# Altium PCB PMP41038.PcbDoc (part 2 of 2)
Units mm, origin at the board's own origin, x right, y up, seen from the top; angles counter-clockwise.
Board outline 101.5 x 48.5 mm, 4 copper layers (Top Layer, Signal Layer 1, Signal Layer 2, Bottom Layer), stack 0.713 mm thick; 126 components, 51 nets, 261 pads, 192 vias.
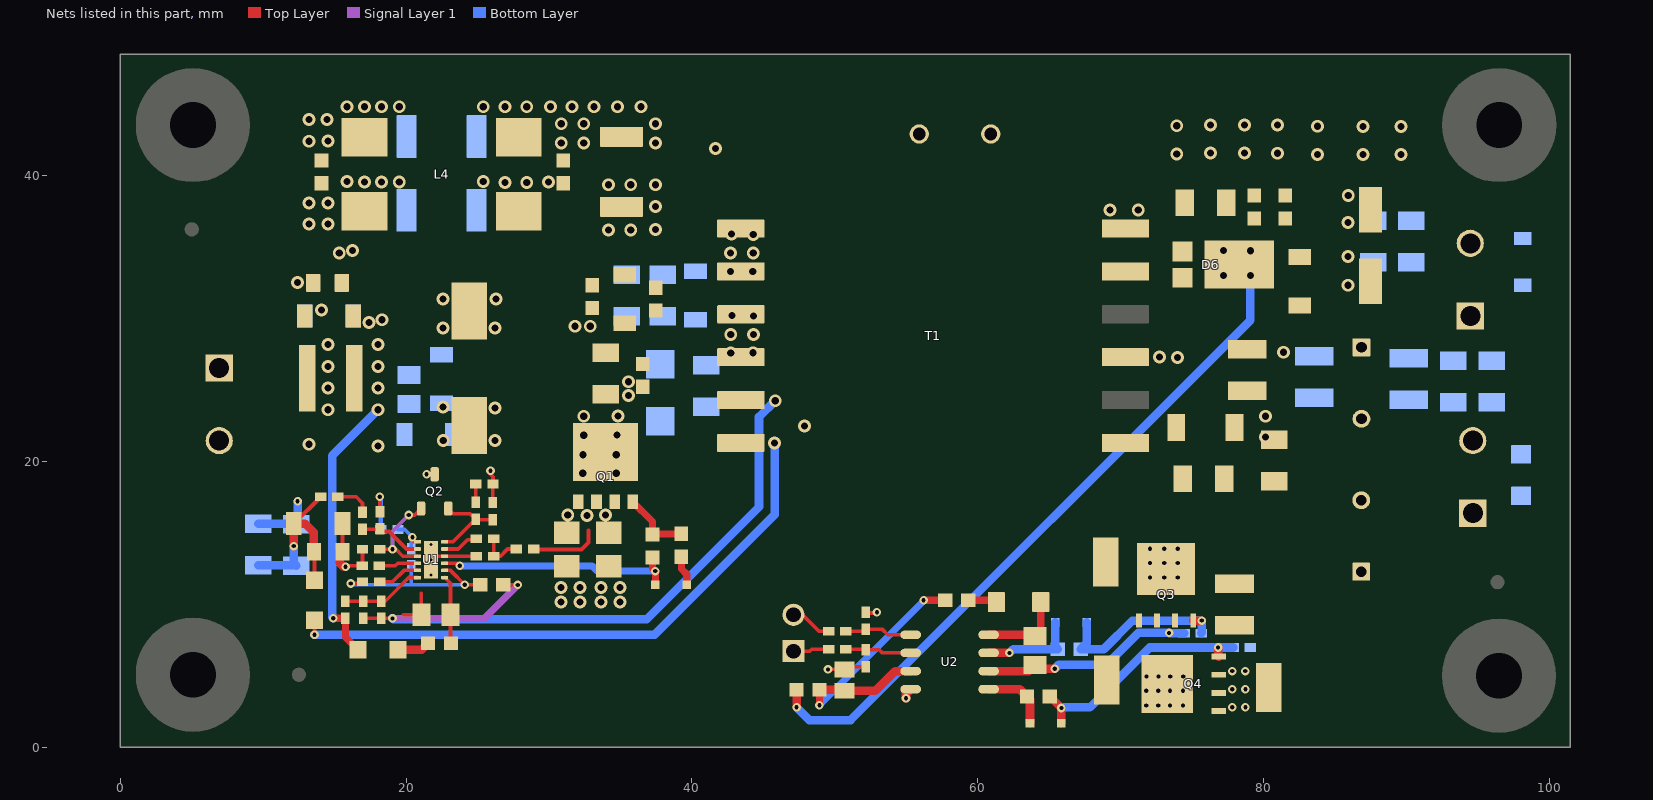
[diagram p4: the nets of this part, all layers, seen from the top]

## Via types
v1: diameter 0.9, hole 0.5, Top Layer to Bottom Layer, 133 vias
v2: diameter 0.6, hole 0.3, Top Layer to Bottom Layer, 56 vias
v3: diameter 0.5, hole 0.2, Top Layer to Bottom Layer, 3 vias

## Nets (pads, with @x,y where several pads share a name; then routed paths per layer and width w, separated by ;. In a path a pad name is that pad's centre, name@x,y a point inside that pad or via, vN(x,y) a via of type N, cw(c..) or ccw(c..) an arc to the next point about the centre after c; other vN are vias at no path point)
12Vo: C19.1 C20.2 C21.1 C23.1 D6.3 D7.1 J3.2 R23.2 R35.2 R36.2 | length 48.1
  Top Layer w0.6: v2(47.333,2.794) R23.2@47.333,4.017 R23.2@47.371,4.055
  Bottom Layer w0.6: v2(47.333,2.794) 48.222,1.905 51.116,1.905 79.096,29.885 v1(79.096,33.013)
  other v1: 77.216,33.02 79.096,34.753 77.216,34.76 85.939,36.728 85.946,38.608
120Vo: C12.2 C13.2 C14.2 C15.2 C16.2 C18.1 C33.1 D1.1 D2.1 J2.2 Q3.5 R37.2 R38.2 TP1.1
  other v1: 80.161,21.708 80.161,23.173
  other v2: 72.065,11.879 73.061,11.879 74.004,11.879 72.066,12.895 73.061,12.895 74.004,12.895 72.066,13.904 73.062,13.904 74.004,13.904
AGND: C22.2 C25.2 C28.2 C29.2 C30.2 C31.2 C38.2 Q2.3 R12.1 R20.2 R21.1 R31.1 R33.1 R34.1 T1.5 | length 65.1
  Top Layer w0.254: C29.2@15.35,13.684 C29.2@15.525,13.859 ; C38.2@15.548,15.658 15.55,15.656 C29.2@15.55,13.684 ; v2@15.88,12.698 16.95,12.698 C28.2@16.95,13.859 ; R12.1@17,9.029 C25.2@18.25,9.029 19.037,9.029 v2(19.049,9.017) ; v2@25.837,19.177 26.086,18.929 C31.2@26.086,18.429 26.075,18.419 C30.2@26.075,17.132 ; C22.2@26.8,11.379 27.794,11.379 v2(27.813,11.361)
  Top Layer w0.3: v2(18.15,17.526) 18.173,17.503 R21.1@18.173,16.49
  Top Layer w0.6: C29.2@15.35,13.684 15.35,12.912 v2@15.633,12.629
  Signal Layer 1 w0.5: v2(19.049,9.017) 25.469,9.017 v2(27.813,11.361)
  Bottom Layer w0.3: v2(18.15,17.526) 18.236,17.44 R20.2@18.236,15.24
  Bottom Layer w0.6: R34.1@9.652,15.637 12.345,15.637 12.407,15.699 v2(12.407,17.224) ; v2(19.049,9.017) 19.095,8.971 30.435,8.971 30.454,8.953 36.83,8.953 44.704,16.827 44.704,23.117 v1(45.844,24.257)
  other v2: 15.763,12.629 21.434,19.107 25.908,19.354
BIAS: C24.1 R6.1 U1.1 | length 4.8
  Top Layer w0.254: U1.1@22.7,11.879 23.106,11.473 C24.1@23.106,9.279 23.106,7.313 R6.1@23.14,7.279
CS: R14.2 U1.5 | length 2.5
  Top Layer w0.254: U1.5@22.7,13.879 23.656,13.879 24.306,14.529 R14.2@24.925,14.529
DPWMH: J4.1 R28.1 | length 2.5
  Top Layer w0.254: J4.1@47.117,6.731 48.26,6.731 48.387,6.858 R28.1@49.573,6.858
DPWML: J4.2 R27.1 | length 2.9
  Top Layer w0.254: J4.2@47.117,9.271 47.752,9.271 48.895,8.128 R27.1@49.573,8.128
FB: R19.1 R21.2 U1.8 | length 4.4
  Top Layer w0.254: R19.1@16.95,15.257 18.14,15.257 R21.2@18.173,15.29 ; R21.2@18.173,15.104 18.805,15.104 20.03,13.879 U1.8@20.8,13.879
GATE: D9.1 R9.1 U1.3 | length 17
  Top Layer w0.254: U1.3@22.7,12.879 23.568,12.879 v2(23.749,12.698)
  Top Layer w0.5: R9.1@37.25,13.289 37.25,12.534 v2(37.449,12.335) D9.1@37.449,11.361
  Bottom Layer w0.5: v2(23.749,12.698) 33.018,12.698 33.382,12.335 v2(37.449,12.335)
GND: C2.2 J1.2 L4.1 L5.1
  other v1: 13.208,36.627 14.525,36.627 13.208,38.1 14.525,38.1 17.09,39.562 18.288,39.562 19.519,39.562 15.875,39.611
HB: C34.1 D10.1 U2.8 | length 5.8
  Top Layer w0.5: C34.1@64.016,7.789 64.423,8.196 D10.1@64.423,10.16
  Top Layer w0.6: U2.8@60.772,7.874 63.931,7.874 C34.1@64.016,7.789
HI: C37.1 R28.2 U2.2 | length 4.7
  Top Layer w0.254: R28.2@50.773,6.858 52.149,6.858 C37.1@52.184,6.823 53.121,6.823 53.34,6.604 U2.2@55.322,6.604
HO: D11.1 R26.1 U2.7 | length 6.9
  Top Layer w0.6: U2.7@60.772,6.604 v2(62.23,6.604)
  Bottom Layer w0.6: v2(62.23,6.604) 62.484,6.858 R26.1@65.621,6.858 65.448,7.031 D11.1@65.448,8.763
HS: C34.2 Q3.1 Q3.2 Q3.3 Q4.5 R25.1 TP2.1 U2.6 | length 15
  Top Layer w0.6: U2.6@60.772,5.334 63.593,5.334 C34.2@64.016,5.757 64.279,5.494 v2(65.405,5.494)
  Bottom Layer w0.6: v2(65.405,5.494) 65.68,5.77 69.016,5.77 71.247,8.001 v2(73.406,8.001) 73.419,7.988 R25.1@74.457,7.988
  other v2: 71.804,2.921 72.64,2.921 73.465,2.921 74.374,2.921 71.804,3.952 72.64,3.952 73.465,3.952 74.374,3.952 71.824,4.953 72.66,4.953 73.485,4.953 74.403,4.953
IS: C26.2 Q1.1 Q1.2 Q1.3 R15.2 R17.2 R18.2 | length 4.9
  Top Layer w0.254: R15.2@28.924,13.879 28.96,13.843 32.278,13.843 32.766,14.331 32.766,15.202
  other v1: 32.66,16.211 31.316,16.256 33.962,16.256 35.573,24.631 35.573,25.583
LI: C36.1 R27.2 U2.1 | length 4.8
  Top Layer w0.254: R27.2@50.773,8.128 52.064,8.128 C36.1@52.184,8.248 53.347,8.248 53.721,7.874 U2.1@55.322,7.874
LO: D12.1 R29.1 U2.5 | length 4.9
  Top Layer w0.254: R29.1@63.335,3.683 R29.1@63.462,3.556
  Top Layer w0.6: U2.5@60.772,4.064 62.954,4.064 R29.1@63.335,3.683 ; R29.1@63.462,3.556 63.67,3.348 D12.1@63.67,1.691
NetC3_1: C3.1 L2.2 L3.1 L4.3
  other v1: 30.861,42.291 32.432,42.291 37.447,42.291 30.861,43.647 32.432,43.647 37.447,43.647 25.4,44.831 26.924,44.831 28.448,44.831 30.099,44.831 31.623,44.831 33.147,44.831 34.798,44.831 36.449,44.831
NetC4_1: C4.1 C5.1 C6.1 L1.1 L3.2
  other v1: 14.525,23.622 14.525,25.146 14.525,26.64 14.525,28.179 14.082,30.607 12.407,32.524 34.158,36.195 35.729,36.195 37.447,36.25 37.447,37.846 34.158,39.37 35.729,39.37 37.447,39.37
NetC10_1: C10.1 R1.1
NetC17_2: C17.2 D4.1 R2.1 R3.1
NetC18_2: C18.2 R5.2
NetC23_2: C23.2 R7.2
NetC26_1: C26.1 R10.1
NetC27_1: C27.1 R14.1 R15.1 | length 3
  Top Layer w0.254: R14.1@26.125,14.529 26.125,13.804 C27.1@26.125,13.379 26.606,13.379 27.106,13.879 R15.1@27.724,13.879
NetC30_1: C30.1 Q2.2 R22.2 U1.6 | length 6.3
  Top Layer w0.254: U1.6@22.7,14.379 23.291,14.379 R22.2@24.866,15.954 ; Q2.2@22.95,16.707 23.31,16.347 24.473,16.347 R22.2@24.866,15.954 ; C30.1@26.075,15.932 24.888,15.932 R22.2@24.866,15.954
NetC31_1: C31.1 R22.1 | length 1.3
  Top Layer w0.254: R22.1@24.866,17.154 24.866,18.409 C31.1@24.886,18.429
NetD2_2: D2.2 R5.1 T1.7
NetD3_1: D3.1 R6.2 | length 2.3
  Top Layer w0.6: D3.1@19.434,6.823 21.084,6.823 R6.2@21.54,7.279
NetD4_2: D4.2 R4.1
NetD6_1: D6.1 D6.2 R7.1 T1.11
NetD8_2: D8.2 T1.6 | length 41.7
  Top Layer w0.254: v2(13.589,7.874) D8.2@13.589,8.887
  Bottom Layer w0.6: v2(13.589,7.874) 37.395,7.874 45.794,16.273 v1(45.794,21.305)
NetD9_2: D9.2 R11.2 | length 2.1
  Top Layer w0.5: R11.2@39.274,13.339 39.274,12.485 39.649,12.11 D9.2@39.649,11.361
NetD10_2: D10.2 R24.2 | length 2
  Top Layer w0.5: R24.2@59.347,10.287 61.196,10.287 D10.2@61.323,10.16
NetD11_2: D11.2 Q3.4 R25.2 R26.2 | length 12.9
  Top Layer w0.6: Q3.4@75.102,8.88 75.116,8.866 v2(75.692,8.866)
  Bottom Layer w0.6: D11.2@67.648,8.763 67.648,7.285 R26.2@67.221,6.858 68.834,6.858 70.842,8.866 v2(75.692,8.866) 75.692,8.023 R25.2@75.657,7.988
NetD12_2: D12.2 Q4.4 R29.2 R30.2 | length 16.7
  Top Layer w0.6: R29.2@65.062,3.556 v2(65.87,2.748) ; D12.2@65.87,1.691 v2(65.87,2.748) ; v2@65.896,2.774 v2(65.87,2.748) ; v2(76.835,6.985) 76.835,6.403 Q4.4@76.888,6.35
  Bottom Layer w0.6: v2(65.87,2.748) 65.915,2.793 67.866,2.793 72.058,6.985 v2(76.835,6.985) R30.2@77.886,6.985
NetQ1_4: Q1.4 R9.2 R11.1 | length 4.9
  Top Layer w0.5: Q1.4@35.867,17.178 37.25,15.794 R9.2@37.25,14.889 37.3,14.939 R11.1@39.274,14.939
NetQ1_5: Q1.5 R4.2 R10.2 T1.3 T1.4
  other v1: 32.365,19.177 34.713,19.181 32.385,20.473 34.713,20.477 32.432,21.844 34.766,21.848 32.432,23.173 34.84,23.176 42.725,27.605 44.295,27.612 42.725,28.902 44.327,28.902 44.327,30.198 42.803,30.226
NetR16_1: R16.1 R19.2 | length 2.5
  Top Layer w0.254: R16.1@15.228,17.526 16.506,17.526 16.95,17.082 R19.2@16.95,16.457
NetR20_1: R20.1 R32.1 U1.7 | length 2.7
  Top Layer w0.254: v2(20.447,14.699) 20.447,14.469 20.536,14.379 U1.7@20.8,14.379
  Bottom Layer w0.254: R20.1@19.436,15.24 19.906,15.24 v2(20.447,14.699) 20.372,14.624 R32.1@20.372,13.894
PGND: C1.2 C3.2 C4.2 C5.2 C6.2 C7.2 C8.2 C9.2 C10.2 C11.2 C24.2 C27.2 C32.2 L4.4 L5.2 R17.1 R18.1 U1.4 U1.13 | length 5.7
  Top Layer w0.254: 19.82,9.279 C24.2@21.074,9.279 21.074,10.787 ; U1.13@22,13.379 U1.4@22.7,13.379 C27.2@24.925,13.379
  other v1: 30.84,10.16 32.169,10.16 33.639,10.16 34.983,10.16 30.84,11.176 32.169,11.176 33.639,11.176 34.983,11.176 18.034,21.086 13.209,21.209 22.606,21.463 26.223,21.463 47.885,22.479 26.223,23.749 22.589,23.806 31.818,29.464 32.891,29.464 17.399,29.739 18.323,29.923 15.32,34.6 16.256,34.76 26.924,39.541 28.448,39.541 29.972,39.562 25.4,39.611 41.656,41.92
  other v3: 21.75,12.054 21.75,13.129 21.75,14.204
PGOOD: R13.1 U1.11 | length 3
  Top Layer w0.254: R13.1@18.15,11.579 19.049,11.579 19.849,12.379 U1.11@20.8,12.379
RT: R33.2 U1.10 | length 2.7
  Top Layer w0.254: R33.2@18.15,12.698 19.25,12.698 19.431,12.879 U1.10@20.8,12.879
SGND: C12.1 C13.1 C14.1 C15.1 C16.1 C19.2 C20.1 C21.2 C32.1 C33.2 C35.2 C36.2 C37.2 D1.2 D7.2 J2.1 J3.1 Q4.1 Q4.2 Q4.3 R30.1 R35.1 R36.1 R37.1 R38.1 T1.9 T1.12 TP3.1 U2.4 | length 4.5
  Top Layer w0.254: v2(49.53,5.449) C35.2@50.673,5.449 50.847,5.623 C37.2@52.184,5.623 ; C35.2@50.566,5.227 C35.2@50.73,5.391 ; C36.2@52.184,9.448 52.434,9.448 52.484,9.398 52.909,9.398 v2(52.959,9.448)
  Top Layer w0.6: v2(54.991,3.429) 54.991,3.733 U2.4@55.322,4.064
  other v1: 74.004,27.292 72.743,27.305 81.407,27.653 85.935,32.337 85.928,34.353 69.279,37.614 71.247,37.614 86.974,41.484 89.641,41.484 83.799,41.497 73.938,41.533 81.005,41.576 76.306,41.594 78.681,41.594 83.799,43.465 86.974,43.451 89.641,43.451 73.938,43.5 81.005,43.543 76.306,43.561 78.681,43.561
  other v2: 77.822,2.793 78.749,2.791 77.822,4.063 78.749,4.061 77.822,5.333 78.74,5.333
SS: C28.1 Q2.1 U1.9 | length 6.8
  Top Layer w0.254: C28.1@18.15,13.859 v2(19.05,13.859) 19.288,13.859 19.768,13.379 U1.9@20.8,13.379 ; v2(20.193,16.256) 20.599,16.256 Q2.1@21.05,16.707
  Signal Layer 1 w0.254: v2(19.05,13.859) 19.05,15.113 v2(20.193,16.256)
UVLO: C25.1 R8.1 R12.2 U1.12 | length 5.7
  Top Layer w0.254: R8.1@15.75,10.229 R12.2@17,10.229 C25.1@18.25,10.229 18.543,10.229 20.193,11.879 U1.12@20.8,11.879
VCC: C22.1 R13.2 R32.2 U1.2 | length 13.1
  Top Layer w0.254: v2(16.129,11.463) 16.834,11.463 R13.2@16.95,11.579 ; U1.2@22.7,12.379 23.107,12.379 v2(24.107,11.379) C22.1@25.2,11.379
  Bottom Layer w0.254: v2(16.129,11.463) 16.213,11.379 20.32,11.379 ; R32.2@20.372,12.694 20.372,11.431 20.32,11.379 ; v2(24.107,11.379) 20.32,11.379
VDD: C35.1 R23.1 R24.1 U2.3 | length 19.9
  Top Layer w0.5: v2(48.933,2.95) R23.1@48.933,4.017 ; v2(56.221,10.287) R24.1@57.747,10.287
  Top Layer w0.6: R23.1@48.933,4.017 50.605,4.017 C35.1@50.673,3.949 52.851,3.949 54.236,5.334 U2.3@55.322,5.334
  Bottom Layer w0.5: v2(48.933,2.95) 56.221,10.238 v2(56.221,10.287)
VIN: C2.1 J1.1 L2.1 L4.2
  other v1: 13.209,42.418 14.525,42.447 13.209,43.942 14.478,43.942 15.875,44.831 17.09,44.831 18.288,44.831 19.519,44.831
VIN_FILTER: C1.1 C7.1 C8.1 C9.1 C11.1 C17.1 D3.2 L1.2 R1.2 R2.2 R3.2 R8.2 T1.1 T1.2 | length 19.4
  Top Layer w0.5: v2(14.91,9.029) R8.2@15.75,9.029 15.75,7.707 D3.2@16.634,6.823
  Bottom Layer w0.6: v2(14.91,9.029) 14.829,9.11 14.829,20.417 v1(18.034,23.622)
  other v1: 18.034,25.146 18.034,26.64 18.034,28.179 22.589,29.337 26.223,29.337 22.589,31.369 26.289,31.369 42.698,33.303 44.267,33.31 42.698,34.6 44.299,34.6 44.299,35.896 42.775,35.924
Vpri: C29.1 C38.1 D8.1 R16.2 R31.2 R34.2 | length 13.3
  Top Layer w0.254: C29.1@13.428,13.684 13.589,13.523 D8.1@13.589,11.853
  Top Layer w0.3: C38.1@12.148,15.658 12.161,15.658 R16.2@14.028,17.526
  Top Layer w0.6: v2(12.148,14.085) C38.1@12.148,15.658 ; C38.1@12.161,15.658 12.928,15.658 13.55,15.036 C29.1@13.55,13.684 C29.1@13.428,13.684
  Bottom Layer w0.6: R34.2@9.652,12.737 R31.2@12.293,12.737 ; v2(12.148,14.085) 12.148,12.881 R31.2@12.293,12.737 ; R31.2@12.319,12.711 R31.2@12.293,12.737
pads on no net: FID1.1 FID2.1 FID3.1 H1.1 H2.1 H3.1 H4.1 H5.0 H6.0 H7.0 H8.0 LBL1.0 T1.8 T1.10

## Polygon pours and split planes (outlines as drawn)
SGND on Top Layer "TOP_LAYER_SGND_P322" (solid, remove dead copper, pour order 322): 75.946,1.524 76.561,0.909 100.457,0.909 100.457,14.351 100.457,32.004 99.06,33.401 92.553,33.401 90.976,34.978 85.257,34.978 81.407,31.127 79.236,28.956 68.58,28.956 68.199,28.575 68.199,26.543 68.58,26.162 80.023,26.162 95.885,26.162 97.282,24.765 97.282,20.066 95.792,18.576 93.252,18.576 90.043,15.367 82.169,15.367 81.534,14.732 81.534,11.239 79.574,9.279 76.533,9.279 75.946,8.692
NetD2_2 on Top Layer "TOP_LAYER_NETD2_2_P298" (solid, remove dead copper, pour order 298): 68.834,19.812 70.883,19.812 71.985,18.71 71.985,17.677 72.39,17.272 74.844,17.272 75.231,17.658 75.231,23.321 74.807,23.745 72.997,23.745 71.985,22.733 68.834,22.733 68.08,21.979 68.08,20.566
NetC23_2 on Top Layer "TOP_LAYER_NETC23_2_P296" (solid, remove dead copper, pour order 296): 78.052,37.328 78.443,37.719 79.566,37.719 80.066,38.219 80.066,39.024 79.617,39.472 76.346,39.472 76.073,39.2 76.073,36.962 76.308,36.728 77.876,36.728 78.052,36.904
NetD8_2 on Top Layer "TOP_LAYER_NETD8_2_P294" (solid, remove dead copper, pour order 294): 41.783,20.066 41.715,20.134 41.715,21.933 42.006,22.225 46.119,22.225 46.482,21.862 46.482,20.477 46.071,20.066
AGND on Top Layer "TOP_LAYER_AGND_P292" (solid, remove dead copper, pour order 292): 41.783,22.987 41.715,23.055 41.715,24.936 41.881,25.103 46.046,25.103 46.348,24.801 46.348,23.393 45.942,22.987
VIN_FILTER on Top Layer "TOP_LAYER_VIN_FILTER_P110" (solid, remove dead copper, pour order 110): 40.35,31.66 45.653,31.66 46.355,32.337 46.355,34.295 46.355,36.87 45.611,37.614 41.812,37.614 38.704,34.506 30.887,34.506 28.832,34.506 27.236,32.91 21.71,32.91 19.177,30.377 19.177,29.522 18.496,28.841 18.48,28.841 15.688,28.841 15.494,28.644 15.494,23.339 15.743,23.091 17.766,23.091 18.88,23.091 22.713,26.924 26.416,26.924 31.152,31.66
VIN on Top Layer "TOP_LAYER_VIN_P084" (solid, remove dead copper, pour order 84): 20.574,40.513 21.021,40.96 21.021,47.178 20.574,47.625 2.794,47.625 0.889,45.72 0.889,25.453 1.958,24.384 6.985,24.384 7.874,25.273 7.874,34.72 13.667,40.513
GND on Top Layer "TOP_LAYER_GND_P082" (solid, remove dead copper, pour order 82): 20.605,40.18 21.021,39.764 21.021,39.718 21.021,36.195 20.576,35.75 14.082,35.75 11.43,33.098 11.43,19.624 10.475,18.669 1.27,18.669 0.889,19.05 0.889,23.123 1.515,23.749 7.112,23.749 8.255,24.892 8.255,34.587 13.848,40.18
SGND on Top Layer "TOP_LAYER_SGND_P064" (solid, remove dead copper, pour order 64): 83.765,39.985 82.007,38.227 81.28,38.227 79.522,39.985 73.231,39.985 72.271,39.025 72.271,35.818 71.696,35.242 68.77,35.242 68.326,35.687 68.326,43.682 69.342,44.698 81.12,44.698 81.136,44.682 90.994,44.682 91.694,43.982 91.694,41.021 90.658,39.985
no net on Top Layer "TOP_LAYER_NONET_P062" (solid, remove dead copper, pour order 62): 67.818,43.776
12Vo on Top Layer "TOP_LAYER_12VO_P060" (solid, remove dead copper, pour order 60): 77.724,35.941 78.486,36.703 78.486,37.396 78.682,37.592 80.627,37.592 82.042,37.592 83.991,39.541 93.009,39.541 93.737,38.813 96.393,38.813 97.028,38.178 97.028,34.544 96.52,34.036 92.931,34.036 91.646,35.32 84.964,35.32 81.325,31.682 76.268,31.682 75.819,32.131 75.819,35.468 76.292,35.941
NetC18_2 on Top Layer "TOP_LAYER_NETC18_2_P056" (solid, remove dead copper, pour order 56): 76.739,17.292 76.415,17.615 76.415,19.541 76.599,19.722 81.142,19.722 81.661,19.202 81.661,17.526 81.427,17.292
120Vo on Top Layer "TOP_LAYER_120VO_P050" (solid, remove dead copper, pour order 50): 68.088,10.414 79.148,10.414 79.629,10.895 79.629,14.692 78.934,15.367 68.206,15.367 67.691,14.866 67.691,10.811
NetD6_1 on Top Layer "TOP_LAYER_NETD6_1_P046" (solid, remove dead copper, pour order 46): 75.329,39.231 74.936,39.624 73.86,39.624 72.94,38.704 72.94,35.427 72.191,34.678 68.658,34.678 68.418,34.438 68.418,32.166 68.961,31.623 74.989,31.623 75.329,31.964 75.329,34.417
HS on Top Layer "TOP_LAYER_HS_P042" (solid, remove dead copper, pour order 42): 72.921,9.596 74.208,9.596 74.45,9.354 74.45,8.068 74.644,7.874 75.187,7.874 75.438,7.623 75.438,7.08 75.438,2.032 75.418,1.614 74.713,0.909 68.613,0.909 67.564,1.958 67.564,9.132 68.028,9.596
PGND on Top Layer "TOP_LAYER_PGND_P040" (solid, remove dead copper, pour order 40): 19.675,10.761 19.675,9.107 19.892,8.89 20.065,8.89 20.21,9.035 20.21,10.16 20.346,10.295 22.479,10.295 22.7,10.516 22.7,12.731 21.645,12.731 20.471,11.557
AGND on Top Layer "TOP_LAYER_AGND_P038" (solid, remove dead copper, pour order 38): 19.622,14.836 22.251,14.836 22.251,16.085 21.25,17.086 21.25,17.469 23.613,17.469 23.876,17.732 23.876,18.669 24.186,18.979 26.162,18.979 26.289,19.106 26.289,19.554 26.158,19.685 15.875,19.685 12.468,19.685 10.668,17.885 10.668,7.747 12.966,5.449 18.276,5.449 19.429,6.602 19.431,9.441 19.221,9.652 18.927,9.652 18.771,9.496 18.771,8.481 18.669,8.381 14.449,8.375 14.443,9.689 14.983,9.689 15.2,9.906 15.196,10.883 16.331,12.018 16.331,12.669 16.079,12.921 14.819,12.921 14.438,12.541 12.735,12.541 12.735,16.404 12.735,17.469 18.791,17.469 18.8,15.658
120Vo on Top Layer "TOP_LAYER_120VO_P034" (solid, remove dead copper, pour order 34): 76.513,25.424 76.743,25.654 95.324,25.654 96.5,24.478 96.5,20.3 95.277,19.077 92.737,19.077 89.813,16.153 86.244,16.153 81.569,20.828 76.81,20.828 76.513,21.125
PGND on Top Layer "TOP_LAYER_PGND_P032" (solid, remove dead copper, pour order 32): 30.113,13.125 30.45,13.462 35.434,13.462 35.701,13.195 35.701,8.509 35.235,8.043 30.576,8.043 30.113,8.513
IS on Top Layer "TOP_LAYER_IS_P030" (solid, remove dead copper, pour order 30): 29.972,17.478 30.573,18.079 34.874,18.079 35.179,17.774 35.179,16.256 35.492,15.943 35.492,14.526 35.189,14.224 30.353,14.224 29.972,14.605
IS on Top Layer "TOP_LAYER_IS_P026" (solid, remove dead copper, pour order 26): 37.003,24.196 37.14,24.196 37.257,24.313 37.257,25.889 37.103,26.044 37.082,26.046 35.373,26.046 35.179,25.853 35.179,24.547 35.531,24.196
NetC26_1 on Top Layer "TOP_LAYER_NETC26_1_P024" (solid, remove dead copper, pour order 24): 32.327,26.624 32.327,28.26 32.595,28.529 37.026,28.529 37.28,28.275 37.28,26.722 36.928,26.37 32.581,26.37
PGND on Top Layer "TOP_LAYER_PGND_P022" (solid, remove dead copper, pour order 22): 36.419,31.369 38.1,31.373 38.377,31.095 38.377,29.188 38.018,28.829 36.368,28.829 32.298,28.829 32.057,29.071 32.057,30.926 32.5,31.369
NetQ1_5 on Top Layer "TOP_LAYER_NETQ1_5_P020" (solid, remove dead copper, pour order 20): 41.29,21.408 41.29,25.103 41.715,25.527 45.325,25.527 46,26.162 46,30.835 45.688,31.147 39.529,31.147 38.862,30.48 38.862,28.644 37.941,27.723 37.941,24.053 37.694,23.806 35.135,23.806 34.925,24.016 34.925,25.356 34.501,25.781 31.384,25.781 31.115,25.512 31.115,18.796 31.369,18.542 37.719,18.542 38.481,19.304 40.894,19.304 41.29,19.7
no net on Top Layer "TOP_LAYER_NONET_P018" (solid, remove dead copper, pour order 18): 24.73,22.352
PGND on Top Layer "TOP_LAYER_PGND_P016" (solid, remove dead copper, pour order 16): 30.226,26.691 32.364,28.829 32.766,29.231 32.766,31.369 31.613,31.369 26.759,26.515 23.154,26.515 22.946,26.515 19.182,22.751 19.103,22.672 12.117,22.672 11.754,22.309 11.754,20.416 12.232,19.939 29.718,19.939 30.226,20.447
NetC4_1 on Top Layer "TOP_LAYER_NETC4_1_P012" (solid, remove dead copper, pour order 12): 32.66,36.25 32.66,39.435 33.475,40.25 33.545,40.18 37.67,40.18 38.377,39.473 38.377,36.271 37.412,35.306 33.694,35.306 33.25,35.75
NetC3_1 on Top Layer "TOP_LAYER_NETC3_1_P008" (solid, remove dead copper, pour order 8): 24.542,45.593 37.622,45.593 38.377,44.838 38.377,41.248 37.629,40.5 24.486,40.5 23.876,41.11 23.876,44.927
PGND on Top Layer "TOP_LAYER_PGND_P002" (solid, remove dead copper, pour order 2): 18.863,30.674 18.863,29.774 18.249,29.16 15.273,29.16 14.807,29.626 14.807,34.866 15.191,35.25 20.592,35.25 21.941,36.599 23.582,36.599 23.876,36.89 23.876,39.534 24.522,40.18 31.707,40.18 32.365,39.522 32.365,36.627 30.639,34.901 28.756,34.901 27.129,33.274 21.463,33.274
NetC4_1 on Top Layer "TOP_LAYER_NETC4_1_P000" (solid, remove dead copper, pour order 0): 14.525,29.393 14.525,29.389 15.191,28.723 15.191,23.366 14.916,23.091 14.225,23.091 12.192,23.091 11.811,23.472 11.811,23.495 11.811,33.098 13.003,34.29 14.21,34.29 14.525,33.975
PGND on Signal Layer 1 "SIGNAL_LAYER_1_PGND_P308" (solid, remove dead copper, pour order 308): 1.016,1.27 1.016,47.117 1.524,47.625 57.404,47.625 58.039,46.99 58.039,13.87 57.123,12.954 46.723,12.954 44.327,10.558 44.327,2.544 43.053,1.27
SGND on Signal Layer 1 "SIGNAL_LAYER_1_SGND_P284" (solid, remove dead copper, pour order 284): 46.736,1.143 45.733,2.146 45.733,9.792 47.371,11.43 57.658,11.43 59.563,13.335 59.563,46.482 60.706,47.625 98.298,47.625 100.711,45.212 100.711,4.018 97.836,1.143
VIN_FILTER on Signal Layer 1 "SIGNAL_LAYER_1_VIN_FILTER_P232" (solid, remove dead copper, pour order 232): 17.792,28.841 17.272,28.321 17.272,23.585 17.766,23.091 18.88,23.091 22.713,26.924 26.416,26.924 31.152,31.66 45.413,31.66 46,32.207 46,34.045 46,35.634 44.931,36.703 42.343,36.703 40.146,34.506 30.887,34.506 28.832,34.506 26.33,32.004 20.804,32.004 19.177,30.377 19.177,29.522 18.496,28.841 18.48,28.841
AGND on Signal Layer 1 "SIGNAL_LAYER_1_AGND_P076" (solid, remove dead copper, pour order 76): 18.161,6.985 18.161,7.023 19.519,8.381 19.519,10.756 20.066,11.303 20.767,11.303 21.021,11.557 21.021,14.286 21.848,15.113 26.58,15.113 26.924,15.457 26.924,19.354 26.593,19.685 12.446,19.685 10.668,17.907 10.668,7.747 11.43,6.985
NetC4_1 on Signal Layer 1 "SIGNAL_LAYER_1_NETC4_1_P152" (solid, remove dead copper, pour order 152): 14.525,29.393 14.525,29.389 15.191,28.723 15.191,23.366 14.916,23.091 14.225,23.091 12.192,23.091 11.811,23.472 11.811,23.495 11.811,33.098 13.003,34.29 14.21,34.29 14.525,33.975
PGND on Signal Layer 1 "SIGNAL_LAYER_1_PGND_P150" (solid, remove dead copper, pour order 150): 18.863,30.674 18.863,29.774 18.249,29.16 15.273,29.16 14.807,29.626 14.807,34.866 15.191,35.25 20.592,35.25 21.941,36.599 23.582,36.599 23.876,36.89 23.876,39.534 24.522,40.18 31.707,40.18 32.365,39.522 32.365,36.627 30.639,34.901 28.756,34.901 26.367,32.512 20.701,32.512
NetC4_1 on Signal Layer 1 "SIGNAL_LAYER_1_NETC4_1_P148" (solid, remove dead copper, pour order 148): 32.66,36.25 32.66,39.435 33.475,40.25 33.545,40.18 37.67,40.18 38.377,39.473 38.377,36.271 37.683,35.577 33.423,35.577 33.25,35.75
IS on Signal Layer 1 "SIGNAL_LAYER_1_IS_P124" (solid, remove dead copper, pour order 124): 30.438,15.973 30.917,15.493 36.431,15.493 37,16.063 37,25.931 36.642,26.289 30.948,26.289 30.474,25.815
NetC3_1 on Signal Layer 1 "SIGNAL_LAYER_1_NETC3_1_P118" (solid, remove dead copper, pour order 118): 24.542,45.593 37.622,45.593 38.377,44.838 38.377,41.248 37.629,40.5 24.486,40.5 23.876,41.11 23.876,44.927
GND on Signal Layer 1 "SIGNAL_LAYER_1_GND_P080" (solid, remove dead copper, pour order 80): 20.605,40.18 21.021,39.764 21.021,39.718 21.021,36.195 20.576,35.75 14.082,35.75 11.43,33.098 11.43,19.624 10.475,18.669 1.27,18.669 0.889,19.05 0.889,23.123 1.515,23.749 7.112,23.749 8.255,24.892 8.255,34.587 13.848,40.18
VIN on Signal Layer 1 "SIGNAL_LAYER_1_VIN_P078" (solid, remove dead copper, pour order 78): 20.574,40.513 21.021,40.96 21.021,47.178 20.574,47.625 2.794,47.625 0.889,45.72 0.889,25.453 1.958,24.384 6.985,24.384 7.874,25.273 7.874,34.72 13.667,40.513
SGND on Signal Layer 2 "SIGNAL_LAYER_2_SGND_P312" (solid, remove dead copper, pour order 312): 46.863,1.143 45.733,2.273 45.733,9.792 47.371,11.43 57.658,11.43 59.563,13.335 59.563,46.355 60.706,47.498 100.457,47.498 100.457,1.143
PGND on Signal Layer 2 "SIGNAL_LAYER_2_PGND_P310" (solid, remove dead copper, pour order 310): 1.016,1.27 1.016,47.117 1.524,47.625 56.896,47.625 58.039,46.482 58.039,13.87 57.123,12.954 46.723,12.954 44.327,10.558 44.327,2.544 43.053,1.27
VIN_FILTER on Signal Layer 2 "SIGNAL_LAYER_2_VIN_FILTER_P306" (solid, remove dead copper, pour order 306): 18.88,23.091 18.58,23.091 17.766,23.091 17.676,23.091 17.227,23.54 17.227,28.276 17.792,28.841 18.496,28.841 19.177,29.522 19.177,29.537 21.644,32.004 26.33,32.004 28.832,34.506 30.887,34.506 39.161,34.506 42.246,37.592 45.529,37.592 46,37.121 46,34.045 46,32.345 45.294,31.66 31.158,31.66 26.422,26.924 22.713,26.924
NetC4_1 on Signal Layer 2 "SIGNAL_LAYER_2_NETC4_1_P304" (solid, remove dead copper, pour order 304): 15.958,29.16 17.336,30.538 18.678,30.538 18.684,30.544 19.633,30.544 21.601,32.512 26.367,32.512 28.756,34.901 30.639,34.901 35.306,34.901 35.306,40.18 31.377,40.18 30.988,39.791 30.988,39.224 30.499,38.735 25.721,38.735 23.876,36.89 23.609,36.627 21.969,36.627 20.592,35.25 15.191,35.25 13.667,33.726 13.667,29.16
NetC3_1 on Signal Layer 2 "SIGNAL_LAYER_2_NETC3_1_P202" (solid, remove dead copper, pour order 202): 24.542,45.593 37.622,45.593 38.377,44.838 38.377,41.248 37.629,40.5 24.486,40.5 23.876,41.11 23.876,44.927
NetC4_1 on Signal Layer 2 "SIGNAL_LAYER_2_NETC4_1_P158" (solid, remove dead copper, pour order 158): 13.963,35.25 19.051,35.25 19.194,35.107 19.194,34.316 15.191,34.316 15.191,28.723 15.191,23.366 14.916,23.091 14.225,23.091 12.192,23.091 11.811,23.472 11.811,23.495 11.811,33.098
NetC4_1 on Signal Layer 2 "SIGNAL_LAYER_2_NETC4_1_P154" (solid, remove dead copper, pour order 154): 32.66,36.25 32.66,39.435 33.405,40.18 37.67,40.18 38.377,39.473 38.377,35.458 37.845,34.925 34.075,34.925 33.25,35.75
VIN on Signal Layer 2 "SIGNAL_LAYER_2_VIN_P104" (solid, remove dead copper, pour order 104): 20.574,40.513 21.021,40.96 21.021,47.178 20.574,47.625 2.794,47.625 0.889,45.72 0.889,25.453 1.958,24.384 6.985,24.384 7.874,25.273 7.874,34.72 13.667,40.513
GND on Signal Layer 2 "SIGNAL_LAYER_2_GND_P102" (solid, remove dead copper, pour order 102): 20.605,40.18 21.021,39.764 21.021,39.718 21.021,36.195 20.576,35.75 14.082,35.75 11.43,33.098 11.43,19.624 10.475,18.669 1.27,18.669 0.889,19.05 0.889,23.123 1.515,23.749 7.112,23.749 8.255,24.892 8.255,34.587 13.848,40.18
SGND on Bottom Layer "BOTTOM_LAYER_SGND_P324" (solid, remove dead copper, pour order 324): 46.355,1.016 45.352,2.019 45.352,9.665 46.99,11.303 57.277,11.303 59.182,13.208 59.182,46.355 60.325,47.498 97.917,47.498 100.33,45.085 100.33,3.891 97.455,1.016
12Vo on Bottom Layer "BOTTOM_LAYER_12VO_P320" (solid, remove dead copper, pour order 320): 77.724,35.941 78.486,36.703 78.486,37.396 78.682,37.592 80.627,37.592 82.042,37.592 83.991,39.541 93.009,39.541 93.737,38.813 98.347,38.813 99.06,38.1 99.06,34.544 98.552,34.036 92.931,34.036 91.646,35.32 84.964,35.32 81.325,31.682 76.268,31.682 75.819,32.131 75.819,35.468 76.292,35.941
NetD4_2 on Bottom Layer "BOTTOM_LAYER_NETD4_2_P128" (solid, remove dead copper, pour order 128): 39.322,21.699 39.304,21.717 36.65,21.717 36.3,22.03 36.3,23.981 36.576,24.257 39.524,24.257 39.878,24.611 39.878,24.638 42.183,24.638 42.246,24.575 42.209,24.537 42.209,21.973 41.934,21.699
120Vo on Bottom Layer "BOTTOM_LAYER_120VO_P248" (solid, remove dead copper, pour order 248): 69.596,14.598 69.596,10.922 70.104,10.414 79.375,10.414 85.471,16.51 90.764,16.51 92.329,18.075 93.314,19.077 98.911,19.077 99.568,19.735 99.568,24.511 98.933,25.146 80.144,25.146
NetQ1_5 on Bottom Layer "BOTTOM_LAYER_NETQ1_5_P240" (solid, remove dead copper, pour order 240): 31.249,19.146 31.249,23.873 31.711,24.335 34.339,24.335 34.868,23.806 34.868,18.442 34.333,17.907 31.75,17.907 31.75,17.927 31.242,18.435
PGND on Bottom Layer "BOTTOM_LAYER_PGND_P228" (solid, remove dead copper, pour order 228): 56.515,27.12 56.505,27.11 56.505,18.823 54.264,16.581 46.061,16.666 45.974,16.579 40.005,10.61 40.005,1.524 38.989,0.508 1.079,0.508 0.635,0.953 0.635,17.724 1.326,18.415 10.5,18.415 10.5,18.44 11.684,19.624 11.684,22.86 21.426,22.86 21.554,22.897 21.557,25.125 22.946,26.515 23.154,26.515 26.515,26.515 31.369,31.369 33.611,31.369 38.583,36.342 38.583,45.586 38.481,45.688 39.783,46.99 53.968,46.99 56.515,44.443
NetC10_1 on Bottom Layer "BOTTOM_LAYER_NETC10_1_P226" (solid, remove dead copper, pour order 226): 19.194,20.325 19.194,24.771 19.43,25.007 21.006,25.007 21.209,24.804 21.209,20.338 20.937,20.066 19.453,20.066
VIN_FILTER on Bottom Layer "BOTTOM_LAYER_VIN_FILTER_P206" (solid, remove dead copper, pour order 206): 45.294,31.66 46,32.345 46,34.045 46,37.121 45.529,37.592 42.246,37.592 39.161,34.506 30.887,34.506 28.832,34.506 26.33,32.004 21.644,32.004 19.177,29.537 19.177,29.522 18.496,28.841 18.48,28.841 15.688,28.841 15.494,28.644 15.494,23.368 15.771,23.091 17.766,23.091 18.58,23.091 18.927,23.438 18.927,24.897 19.303,25.273 19.675,25.273 21.068,25.279 22.713,26.924 26.422,26.924 31.158,31.66
NetC3_1 on Bottom Layer "BOTTOM_LAYER_NETC3_1_P204" (solid, remove dead copper, pour order 204): 24.542,45.593 37.622,45.593 38.377,44.838 38.377,41.248 37.629,40.5 24.486,40.5 23.876,41.11 23.876,44.927
NetC4_1 on Bottom Layer "BOTTOM_LAYER_NETC4_1_P164" (solid, remove dead copper, pour order 164): 15.191,29.457 15.191,23.366 14.916,23.091 14.225,23.091 12.192,23.091 11.811,23.472 11.811,23.495 11.811,33.098 13.872,35.159 15.191,35.159
NetC4_1 on Bottom Layer "BOTTOM_LAYER_NETC4_1_P162" (solid, remove dead copper, pour order 162): 30.639,34.901 35.306,34.901 35.306,40.18 24.522,40.18 23.876,39.534 23.876,36.89 23.609,36.627 21.969,36.627 20.592,35.25 15.191,35.25 13.667,33.726 13.667,29.16 18.249,29.16 18.863,29.774 21.601,32.512 26.367,32.512 28.756,34.901
NetC4_1 on Bottom Layer "BOTTOM_LAYER_NETC4_1_P160" (solid, remove dead copper, pour order 160): 32.66,36.25 32.66,39.435 33.405,40.18 37.67,40.18 38.377,39.473 38.377,35.656 37.646,34.925 34.075,34.925 33.25,35.75
NetQ1_5 on Bottom Layer "BOTTOM_LAYER_NETQ1_5_P130" (solid, remove dead copper, pour order 130): 41.485,28.658 40.259,27.432 40.259,26.319 40.543,26.035 45.395,26.035 46,26.64 46,30.642 45.527,31.115 41.783,31.115 41.485,30.817
NetC17_2 on Bottom Layer "BOTTOM_LAYER_NETC17_2_P126" (solid, remove dead copper, pour order 126): 41.03,28.965 39.37,27.305 39.37,25.622 38.755,25.007 36.842,25.007 36.449,25.4 36.449,26.289 34.25,28.488 34.249,31.005 34.613,31.369 40.542,31.369 41.03,30.881
VIN on Bottom Layer "BOTTOM_LAYER_VIN_P108" (solid, remove dead copper, pour order 108): 20.574,40.513 21.021,40.96 21.021,47.178 20.574,47.625 2.794,47.625 0.889,45.72 0.889,25.453 1.958,24.384 6.985,24.384 7.874,25.273 7.874,34.72 13.667,40.513
GND on Bottom Layer "BOTTOM_LAYER_GND_P106" (solid, remove dead copper, pour order 106): 20.605,40.18 21.021,39.764 21.021,39.718 21.021,36.195 20.576,35.75 14.082,35.75 11.43,33.098 11.43,19.624 10.475,18.669 1.27,18.669 0.889,19.05 0.889,23.123 1.515,23.749 7.112,23.749 8.255,24.892 8.255,34.587 13.848,40.18

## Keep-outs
Keep-Out Layer:
  text ".Layer_Name" at 14.656,-21.806 h1.52

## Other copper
Top Layer:
  rectangle net AGND: 21.25,14.224 22.251,15.494
  region: 18.161,7.874
  region: 17.653,7.493
  text ".Layer_Name" at 14.656,-21.806 h1.52
Signal Layer 1:
  pour cut-out: 12.7,13.943
Bottom Layer:
  region net PGND: 15.732,29.16 15.666,29.227 15.666,30.984 15.849,31.168 18.378,31.168 18.796,30.75 18.796,29.616 18.34,29.16 18.249,29.16
  region net PGND: 23.965,36.378 23.965,39.623 24.474,40.132 30.272,40.132 30.682,39.722 30.682,39.302 29.861,38.481 27.069,38.481 25.876,37.288 25.876,36.29 25.586,36 24.343,36
  text ".Layer_Name" at 14.656,-21.806 h1.52

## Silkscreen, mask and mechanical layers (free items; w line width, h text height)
Top Overlay:
  text "PMP41038E1" at 10.389,1.27 h2.75
  text ".Layer_Name" at 14.656,-21.806 h1.52
Bottom Overlay:
  text ".Layer_Name" at 14.656,-21.806 h1.52
Top Paste:
  text ".Layer_Name" at 14.656,-21.806 h1.52
Bottom Paste:
  text ".Layer_Name" at 14.656,-21.806 h1.52
Top Solder:
  text ".Layer_Name" at 14.656,-21.806 h1.52
  text ".Layer_Name" at 14.656,-21.806 h1.52
Bottom Solder:
  text ".Layer_Name" at 14.656,-21.806 h1.52
Drill Guide:
  text ".Layer_Name" at 14.656,-21.806 h1.52
M1 Board Outline:
  the board outline again, w0.254
  text ".Layer_Name" at 14.656,-21.806 h1.52
M2 Board Dimensions:
  rectangle: 0,-6.985 3.175,-3.81
  rectangle: 3.175,-10.16 12.7,-6.985
  lines w0.178: 0,-6.985 25.4,-6.985 ; 3.175,-10.16 3.175,-3.81 ; 6.35,-10.16 6.35,-3.81 ; 12.7,-10.16 12.7,-3.81 ; 19.05,-10.16 19.05,-3.81 ; 0,-10.16 25.4,-10.16 25.4,-3.81 0,-3.81 0,-10.16
  text ".Layer_Name" at 14.656,-21.806 h1.52
M3 3D STEP Top:
  text ".Layer_Name" at 14.656,-21.806 h1.52
M4 3D STEP Bottom:
  text ".Layer_Name" at 14.656,-21.806 h1.52
M5 Assembly Top:
  lines w0.254: -7.417,-23.626 160.223,-23.626 ; -7.417,-18.462 160.274,-18.462 ; -7.417,-13.297 -7.417,-28.791 94.31,-28.791 160.274,-28.791 160.274,-13.297 -7.404,-13.297 -7.404,-28.791 32.614,-28.791 ; 55.194,-28.791 55.194,-13.297 ; 87.376,-18.462 87.376,-13.297 ; 108.712,-18.462 108.712,-13.297 ; 124.511,-28.956 124.511,-23.804
  text "COMPONENTS MARKED 'DNP' SHOULD NOT BE POPULATED." at 29.299,-8.09 h1.52
  text "ASSEMBLY VARIANT:" at 29.286,-11.024 h1.52
  text ".VariantName" at 55.601,-11.024 h1.52
  text "PCB VIEWED FROM TOP SIDE" at -5.804,-16.654 h1.52
  text "BOARD #:" at 57.099,-16.654 h1.52
  text ".PRJ_Number" at 70.955,-16.654 h1.52
  text "REV:" at 92.405,-16.654 h1.52
  text ".PCB_Rev" at 99.809,-16.654 h1.52
  text "SVN REV:" at 113.69,-16.654 h1.52
  text ".VersionControl_RevNumber" at 126.543,-16.654 h1.52
  text "TID #:" at 57.099,-21.819 h1.52
  text ".TID" at 70.955,-21.819 h1.52
  text "PLOT NAME =" at -5.804,-27.034 h1.52
  text ".plot_File_Name" at 14.656,-27.034 h1.52
  text "GENERATED    :" at 57.15,-27.034 h1.52
  text ".Print_Date" at 79.235,-27.034 h1.52
  text ".Print_Time" at 97.752,-27.034 h1.52
  text "TEXAS INSTRUMENTS" at 129.87,-27.034 h1.52
M6 Assembly Bottom:
  lines w0.254: -7.429,-18.474 160.261,-18.474 ; -7.379,-23.639 160.261,-23.639 ; 28.334,-28.969 28.334,-23.817 ; 44.133,-18.474 44.133,-13.31 ; 65.468,-18.474 65.468,-13.31 ; 97.65,-28.804 97.65,-13.31 ; 120.231,-28.804 160.249,-28.804 160.249,-13.31 -7.429,-13.31 -7.429,-28.804 58.534,-28.804 160.261,-28.804 160.261,-13.31
  text "COMPONENTS MARKED 'DNP' SHOULD NOT BE POPULATED." at 154.991,-8.077 h1.52
  text ".VariantName" at 128.473,-11.024 h1.52
  text "ASSEMBLY VARIANT:" at 154.864,-11.024 h1.52
  text ".VersionControl_RevNumber" at 26.302,-16.667 h1.52
  text "SVN REV:" at 39.154,-16.667 h1.52
  text ".PCB_Rev" at 53.035,-16.667 h1.52
  text "REV:" at 60.439,-16.667 h1.52
  text ".PRJ_Number" at 81.89,-16.667 h1.52
  text "BOARD #:" at 95.745,-16.667 h1.52
  text "PCB VIEWED FROM BOTTOM SIDE" at 158.648,-16.667 h1.52
  text ".TID" at 81.89,-21.831 h1.52
  text "TID #:" at 95.745,-21.831 h1.52
  text "TEXAS INSTRUMENTS" at 22.974,-27.047 h1.52
  text ".Print_Time" at 55.093,-27.047 h1.52
  text ".Print_Date" at 73.609,-27.047 h1.52
  text "GENERATED    :" at 95.694,-27.047 h1.52
  text ".plot_File_Name" at 138.189,-27.047 h1.52
  text "PLOT NAME =" at 158.648,-27.047 h1.52
M9 Title Sheet:
  drawing of 57 lines, arcs and shapes, not listed
  text "1" at 18.792,204.127 h1.78
  text "2" at 82.182,204.127 h1.78
  text "3" at 145.411,204.127 h1.78
  text "4" at 209.08,204.127 h1.78
  text "5" at 272.555,204.127 h1.78
  text "6" at 336.182,204.127 h1.78
  text "A" at -10.579,175.095 h1.78
  text "A" at 365.341,175.095 h1.78
  text "B" at -10.579,114.643 h1.78
  text "B" at 365.341,114.643 h1.78
  text "C" at -10.579,54.318 h1.78
  text "C" at 365.341,54.318 h1.78
  text "PROJECT TITLE:" at 288.125,7.048 h1.14
  text ".PRJ_Title" at 289.395,3.662 h1.78
  text "DESIGNED FOR:" at 288.125,-0.597 h1.14
  text ".PRJ_Customer" at 289.395,-4.153 h1.78
  text "D" at -10.579,-5.88 h1.78
  text "D" at 365.341,-5.88 h1.78
  text "FILE NAME:" at 288.125,-8.217 h1.14
  text ".PCB_File_Name_No_Path" at 289.395,-11.265 h1.78
  text "Texas Instruments (TI) and/or its licensors do not warrant the accuracy or completeness of this specification" at 161.9,-15.376 h1.14
  text "ENGINEER:" at 288.125,-15.583 h1.14
  text "LAYOUT BY:" at 326.352,-15.583 h1.14
  text "or any information contained therein. TI and/or its licensors do not warrant that this design will meet" at 160.757,-18.237 h1.14
  text ".PRJ_Engineer" at 289.395,-19.52 h1.78
  text ".PCB_Layout" at 327.635,-19.52 h1.78
  text "the specifications, will be suitable for your application or fit for any particular purpose, or will operate in" at 160.757,-21.099 h1.14
  text ".Layer_Name" at 14.656,-21.806 h1.52
  text "ALTIUM DESIGNER VERSION:" at 326.352,-23.457 h1.14
  text "an implementation. TI and/or its licensors do not warrant that the design is production worthy. You should" at 160.757,-23.961 h1.14
  text "completely validate and test your design implementation to confirm the system functionality for your application." at 161.9,-26.822 h1.14
  text ".print_Scale" at 289.395,-26.843 h1.78
  text ".Application_BuildNumber" at 327.635,-26.843 h1.78
  text "1" at 18.792,-32.093 h1.78
  text "2" at 82.182,-32.093 h1.78
  text "3" at 145.411,-32.093 h1.78
  text "4" at 209.08,-32.093 h1.78
  text "5" at 272.555,-32.093 h1.78
  text "6" at 336.182,-32.093 h1.78
M10 Fab Notes:
  drawing of 189 lines, arcs and shapes, not listed
  text "DESIGN INFORMATION" at 314.503,161.447 h1.52
  text "MIN. TRACK WIDTH:" at 298.131,158.091 h1.52
  text "8" at 325.976,158.091 h1.52
  text "MIL" at 329.907,158.091 h1.52
  text "7.874" at 321.75,155 h1.52
  text "MIN. CLEARANCE:" at 298.131,154.938 h1.52
  text "MIL" at 329.907,154.938 h1.52
  text "MIN. VIA PAD SIZE:" at 298.131,151.785 h1.52
  text "24" at 325.214,151.785 h1.52
  text "MIL" at 329.907,151.785 h1.52
  text "0.05mm (2MIL)" at 315.784,148.486 h1.52
  text "MINIMUM ANNULAR RING" at 289.769,148.277 h1.52
  text "EXTERNAL" at 333.768,148.277 h1.52
  text "PER" at 294.849,145.48 h1.52
  text "IPC-D-275 CLASS 2 LEVEL C" at 300.437,145.48 h1.52
  text "MIL, HOLES" at 338.238,142.928 h1.52
  text "+/-" at 328.27,142.709 h1.52
  text "+/-" at 349.961,142.709 h1.52
  text "REGISTRATION TOLERANCES:" at 289.769,142.682 h1.52
  text "METAL" at 320.243,142.682 h1.52
  text "5" at 334.879,142.683 h1.52
  text "3" at 356.037,142.683 h1.52
  text "MIL" at 358.99,142.682 h1.52
  text "HOLE SIZE TOLERANCE (UNLESS OTHERWISE SPECIFIED):" at 289.769,140.185 h1.52
  text "+/-" at 349.961,140.112 h1.52
  text "3" at 356.037,140.085 h1.52
  text "MIL" at 358.99,140.085 h1.52
  text "MATERIAL:" at 287.87,136.589 h1.52
  text "FR-4 High Tg" at 312.926,133.324 h1.52
  text "X" at 309.257,133.122 h1.52
  text "FR-408" at 298.563,133.007 h1.52
  text "OTHER" at 336.358,133.007 h1.52
  text "62 MIL (1.6mm) +/-10%" at 306.694,129.374 h1.52
  text "X" at 303.643,129.312 h1.52
  text "THICKNESS:" at 289.769,129.165 h1.52
  text "OTHER" at 339.33,129.165 h1.52
  text "TOLERANCE:" at 289.769,125.652 h1.52
  text "X" at 311.314,125.652 h1.52
  text "ANSI IPC-6012 TYPE 3 CLASS 2" at 315.836,125.652 h1.52
  text "OTHER +/-" at 315.835,121.989 h1.52
  text "BOW & TWIST:" at 289.769,118.302 h1.52
  text "X" at 311.314,118.302 h1.52
  text "ANSI IPC-6012 TYPE 3 CLASS 2" at 315.836,118.302 h1.52
  text "OTHER +/-" at 315.835,114.576 h1.52
  text "DRILLING:" at 287.87,111.258 h1.52
  text "NC_DRILL FILES" at 332.599,108.586 h1.52
  text "REFERENCE:" at 289.769,108.486 h1.52
  text "X" at 306.463,108.484 h1.52
  text "AS SHOWN" at 310.984,108.486 h1.52
  text "X" at 329.348,108.486 h1.52
  text "OTHER" at 340.168,104.873 h1.52
  text "PTH COPPER THICKNESS:" at 289.761,104.783 h1.52
  text "X" at 318.697,104.783 h1.52
  text "20-30 um" at 321.948,104.783 h1.52
  text "BOARD FINISH:" at 287.87,101.034 h1.52
  text "SILKSCREEN:" at 291.812,98.237 h1.52
  text "X" at 316.14,98.237 h1.52
  text "TOP" at 319.112,98.237 h1.52
  text "X" at 329.094,98.237 h1.52
  text "BOTTOM" at 332.091,98.237 h1.52
  text "SILKSCREEN COLOR:" at 291.812,94.295 h1.52
  text "X" at 316.115,94.295 h1.52
  text "WHITE" at 319.112,94.295 h1.52
  text "OTHER" at 332.091,94.295 h1.52
  text "X" at 319.442,90.652 h1.52
  text "GREEN" at 322.439,90.652 h1.52
  text "OTHER" at 338.136,90.652 h1.52
  text "SOLDER RESIST COLOR:" at 291.812,90.477 h1.52
  text "X" at 319.442,86.734 h1.52
  text "MATTE" at 322.439,86.734 h1.52
  text "SEMI-GLOSS" at 338.125,86.717 h1.52
  text "IMMERSION GOLD (ENIG)" at 314.819,82.345 h1.52
  text "ENEPIG" at 348.793,82.162 h1.52
  text "SURFACE FINISH:" at 287.87,82.136 h1.52
  text "X" at 310.298,82.136 h1.52
  text "IMM. TIN/SILVER OR EQUIV" at 296.24,78.649 h1.52
  text "OTHER" at 332.599,78.549 h1.52
  text "ARRAY/PANEL:" at 287.87,74.602 h1.52
  text "CUT AND TRIM PER M1 BOARD OUTLINE" at 314.819,74.393 h1.52
  text "N.C. ROUTE" at 314.819,70.94 h1.52
  text "X" at 332.295,70.94 h1.52
  text "V. SCORE" at 336.816,70.94 h1.52
  text "CERTIFICATION:" at 287.87,67.66 h1.52
  text "MATERIALS AND WORKMANSHIP FOR ALL PCBS" at 306.285,67.66 h1.52
  text "TO MEET OR EXCEED THE REQUIREMENTS OF:" at 306.285,65.271 h1.52
  text "X" at 297.078,62.003 h1.52
  text "ANSI IPC-A-600F CLASS ->" at 300.329,62.003 h1.52
  text "X" at 342.188,62.003 h1.52
  text "2" at 344.982,62.003 h1.52
  text "1" at 336.981,61.965 h1.52
  text "3" at 353.973,61.965 h1.52
  text "X" at 317.702,58.252 h1.52
  text "RoHS" at 320.953,58.252 h1.52
  text "OTHER" at 337.321,58.252 h1.52
  text "PER ORDER" at 347.407,58.252 h1.52
  text "ALL BOARDS MUST MEET OR EXCEED UL94-V0 REQUIREMENTS." at 288.569,54.345 h1.52
  text "PCB MUST BEAR THE UL94V-0 UL REGISTERED MATERIAL ID NUMBER" at 288.569,51.397 h1.52
  text "ADDITIONAL REQUIREMENTS:" at 287.87,47.094 h1.52
  text "MICROSECTION:" at 289.769,44.373 h1.52
  text "YES" at 312.775,44.373 h1.52
  text "REQUIRED" at 334.657,40.707 h1.52
  text "BARE BOARD ELEC. TEST:" at 289.769,40.634 h1.52
  text "NONE" at 322.935,40.634 h1.52
  text "X" at 331.66,40.634 h1.52
  text "PER ORDER" at 349.693,40.634 h1.52
  text "XX MIL VIAS REQUIRE NON-CONDUCTIVE FILL AND PLANARIZE" at 294.04,35.428 h1.5
  text "XX MIL VIAS REQUIRE CONDUCTIVE FILL AND PLANARIZE" at 294.243,32.787 h1.52
  text "OUTER XX MIL TRACES REQUIRE 50 OHM SINGLE-ENDED IMPEDANCE" at 294.218,28.637 h1.47
  text "LAYER 2 & 3 (INNER LAYERS) XX MIL WIDE, XX MIL SPACE / TRACES REQUIRE 100 OHM DIFFERENTIAL IMPEDANCE" at 294.015,22.65 h1.52
  text ".Layer_Name" at 14.656,-21.806 h1.52
M11 Gerber Information:
  lines w0.254: -7.417,-23.626 160.223,-23.626 ; -7.417,-18.462 160.274,-18.462 ; -7.417,-13.297 -7.417,-28.791 94.31,-28.791 160.274,-28.791 160.274,-13.297 -7.404,-13.297 -7.404,-28.791 32.614,-28.791 ; 55.194,-28.791 55.194,-13.297 ; 87.376,-18.462 87.376,-13.297 ; 108.712,-18.462 108.712,-13.297 ; 124.511,-28.956 124.511,-23.804
  text "ALL ARTWORK VIEWED FROM TOP SIDE" at -5.804,-16.654 h1.52
  text "BOARD #:" at 57.099,-16.654 h1.52
  text ".PRJ_Number" at 70.955,-16.654 h1.52
  text "REV:" at 92.405,-16.654 h1.52
  text ".PCB_Rev" at 99.809,-16.654 h1.52
  text "SVN REV:" at 113.69,-16.654 h1.52
  text ".VersionControl_RevNumber" at 126.543,-16.654 h1.52
  text "LAYER NAME =" at -5.804,-21.806 h1.52
  text "TID #:" at 57.099,-21.819 h1.52
  text ".TID" at 70.955,-21.819 h1.52
  text "PLOT NAME =" at -5.804,-27.034 h1.52
  text ".plot_File_Name" at 14.656,-27.034 h1.52
  text "GENERATED    :" at 57.15,-27.034 h1.52
  text ".Print_Date" at 79.235,-27.034 h1.52
  text ".Print_Time" at 97.752,-27.034 h1.52
  text "TEXAS INSTRUMENTS" at 129.87,-27.034 h1.52
M12 Stackup:
  drawing of 295 lines, arcs and shapes, not listed
  text "Layer" at 249.215,189.165 h1.52
  text "Name" at 259.626,189.165 h1.52
  text "Material" at 283.496,189.165 h1.52
  text "Thickness" at 305.334,189.165 h1.52
  text "Constant" at 321.84,189.165 h1.52
  text "Board Layer Stack" at 336.314,189.165 h1.52
  text "1" at 249.215,186.117 h1.52
  text "Top Overlay" at 259.626,186.117 h1.52
  text "2" at 249.215,183.069 h1.52
  text "Top Solder" at 259.626,183.069 h1.52
  text "Solder Resist" at 283.496,183.069 h1.52
  text "0.40mil" at 305.334,183.069 h1.52
  text "3.5" at 321.84,183.069 h1.52
  text "3" at 249.215,180.021 h1.52
  text "Top Layer" at 259.626,180.021 h1.52
  text "Copper" at 283.496,180.021 h1.52
  text "1.40mil" at 305.334,180.021 h1.52
  text "4" at 249.215,176.973 h1.52
  text "Dielectric1" at 259.626,176.973 h1.52
  text "7.48mil" at 305.334,176.973 h1.52
  text "4.2" at 321.84,176.973 h1.52
  text "5" at 249.215,173.925 h1.52
  text "Signal Layer 1" at 259.626,173.925 h1.52
  text "Copper" at 283.496,173.925 h1.52
  text "1.42mil" at 305.334,173.925 h1.52
  text "6" at 249.215,170.877 h1.52
  text "Dielectric 4" at 259.626,170.877 h1.52
  text "7.48mil" at 305.334,170.877 h1.52
  text "4.2" at 321.84,170.877 h1.52
  text "7" at 249.215,167.829 h1.52
  text "Signal Layer 2" at 259.626,167.829 h1.52
  text "Copper" at 283.496,167.829 h1.52
  text "1.42mil" at 305.334,167.829 h1.52
  text "8" at 249.215,164.781 h1.52
  text "Dielectric 7" at 259.626,164.781 h1.52
  text "7.48mil" at 305.334,164.781 h1.52
  text "4.2" at 321.84,164.781 h1.52
  text "9" at 249.215,161.733 h1.52
  text "Bottom Layer" at 259.626,161.733 h1.52
  text "Copper" at 283.496,161.733 h1.52
  text "1.40mil" at 305.334,161.733 h1.52
  text "10" at 249.215,158.685 h1.52
  text "Bottom Solder" at 259.626,158.685 h1.52
  text "Solder Resist" at 283.496,158.685 h1.52
  text "0.40mil" at 305.334,158.685 h1.52
  text "3.5" at 321.84,158.685 h1.52
  text "11" at 249.215,155.637 h1.52
  text "Bottom Overlay" at 259.626,155.637 h1.52
  text ".Layer_Name" at 14.656,-21.806 h1.52
M13 Component Bodies Top:
  text ".Layer_Name" at 14.656,-21.806 h1.52
M14 Component Bodies Bottom:
  text ".Layer_Name" at 14.656,-21.806 h1.52
M15 Courtyards Top:
  text ".Layer_Name" at 14.656,-21.806 h1.52
M16 Courtyards Bottom:
  text ".Layer_Name" at 14.656,-21.806 h1.52
Drill Drawing:
  circle w0.254: c136.238,64.517 r0.702
  lines w0.254: 135.537,66.973 136.94,66.973 136.94,68.377 135.537,68.377 135.537,66.973 ; 135.537,70.131 136.94,70.131 136.94,71.534 135.537,71.534 135.537,70.131 ; 135.537,73.639 135.888,73.639 136.238,73.289 136.589,73.639 136.94,73.639 136.589,73.99 136.94,74.341 136.589,74.341 136.238,74.692 135.888,74.341 135.537,74.341 135.888,73.99 135.537,73.639 ; 135.537,77.85 136.94,77.85 136.238,76.446 135.537,77.85 ; 135.537,79.604 135.537,79.955 135.888,80.306 135.537,80.657 135.537,81.007 135.888,81.007 136.238,80.657 136.589,81.007 136.94,81.007 136.94,80.657 136.589,80.306 136.94,79.955 136.94,79.604 136.589,79.604 136.238,79.955 135.888,79.604 135.537,79.604 ; 135.537,83.463 136.238,82.762 136.94,83.463 136.238,84.165 135.537,83.463 ; 135.537,85.919 136.238,86.27 136.94,85.919 136.589,86.621 136.94,87.323 136.238,86.972 135.537,87.323 135.888,86.621 135.537,85.919 ; 135.817,70.412 136.659,70.412 136.659,71.254 135.817,71.254 135.817,70.412
  lines w0.305: 134.264,62.868 216.344,62.868 ; 134.264,88.13 216.344,88.13 ; 142.846,59.71 142.846,91.288 ; 151.279,59.71 151.279,91.288 ; 167.448,59.71 167.448,91.288 ; 174.03,59.71 174.03,91.288 ; 183.559,59.71 183.559,91.288 ; 201.957,59.71 201.957,91.288 ; 134.264,59.71 216.344,59.71 216.344,91.288 134.264,91.288 134.264,59.71
  text "Symbol" at 136.159,89.077 h1.83
  text "Quantity" at 143.793,89.077 h1.83
  text "Finished Hole Size" at 152.226,89.077 h1.83
  text "Plated" at 168.395,89.077 h1.83
  text "Hole Type" at 174.977,89.077 h1.83
  text "Drill Layer Pair" at 184.506,89.077 h1.83
  text "Hole Tolerance" at 202.904,89.077 h1.83
  text "3" at 143.793,85.919 h1.52
  text "7.87mil (0.200mm)" at 152.226,85.919 h1.52
  text "PTH" at 168.395,85.919 h1.52
  text "Round" at 174.977,85.919 h1.52
  text "Top Layer - Bottom Layer" at 184.506,85.919 h1.52
  text "56" at 143.793,82.762 h1.52
  text "11.81mil (0.300mm)" at 152.226,82.762 h1.52
  text "PTH" at 168.395,82.762 h1.52
  text "Round" at 174.977,82.762 h1.52
  text "Top Layer - Bottom Layer" at 184.506,82.762 h1.52
  text "133" at 143.793,79.604 h1.52
  text "19.69mil (0.500mm)" at 152.226,79.604 h1.52
  text "PTH" at 168.395,79.604 h1.52
  text "Round" at 174.977,79.604 h1.52
  text "Top Layer - Bottom Layer" at 184.506,79.604 h1.52
  text "4" at 143.793,76.446 h1.52
  text "29.53mil (0.750mm)" at 152.226,76.446 h1.52
  text "PTH" at 168.395,76.446 h1.52
  text "Round" at 174.977,76.446 h1.52
  text "Top Layer - Bottom Layer" at 184.506,76.446 h1.52
  text "2" at 143.793,73.289 h1.52
  text "35.43mil (0.900mm)" at 152.226,73.289 h1.52
  text "PTH" at 168.395,73.289 h1.52
  text "Round" at 174.977,73.289 h1.52
  text "Top Layer - Bottom Layer" at 184.506,73.289 h1.52
  text "2" at 143.793,70.131 h1.52
  text "40.00mil (1.016mm)" at 152.226,70.131 h1.52
  text "PTH" at 168.395,70.131 h1.52
  text "Round" at 174.977,70.131 h1.52
  text "Top Layer - Bottom Layer" at 184.506,70.131 h1.52
  text "6" at 143.793,66.973 h1.52
  text "55.12mil (1.400mm)" at 152.226,66.973 h1.52
  text "PTH" at 168.395,66.973 h1.52
  text "Round" at 174.977,66.973 h1.52
  text "Top Layer - Bottom Layer" at 184.506,66.973 h1.52
  text "4" at 143.793,63.815 h1.52
  text "125.98mil (3.200mm)" at 152.226,63.815 h1.52
  text "PTH" at 168.395,63.815 h1.52
  text "Round" at 174.977,63.815 h1.52
  text "Top Layer - Bottom Layer" at 184.506,63.815 h1.52
  text "210 Total" at 143.793,60.658 h1.52
  text ".Layer_Name" at 14.656,-21.806 h1.52
M17 Embedded Cavity:
  text ".Layer_Name" at 14.656,-21.806 h1.52
M18 Embedded Assembly:
  text ".Layer_Name" at 14.656,-21.806 h1.52
M19 Embedded Keepout:
  text ".Layer_Name" at 14.656,-21.806 h1.52

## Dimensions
0,-10.16 to 25.4,-10.16 on M2 Board Dimensions
0,0 to 101.5,0 on M2 Board Dimensions
0,0 to 0,48.5 on M2 Board Dimensions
